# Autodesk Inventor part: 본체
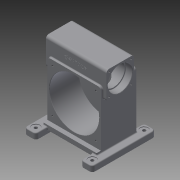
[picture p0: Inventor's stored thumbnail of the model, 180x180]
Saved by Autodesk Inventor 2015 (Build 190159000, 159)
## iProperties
Created: 2025-06
Part Number: 본체
Material: 일반
Document SubType Name: Modeling
Designer: User
Density: 1 g/cm^3
Appearance: 기본값
Author: User
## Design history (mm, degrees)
sketch "스케치4"
  geometry: L1 (-118, 110)-(-78, 110); L2 (-78, 110)-(-78, -110); L3 (-78, -110)-(-118, -110); L4 (-118, -110)-(-118, 110); L5 (78, 110)-(118, 110); L6 (118, 110)-(118, -110); L7 (118, -110)-(78, -110); L8 (78, -110)-(78, 110); 3 further points
  constraints: 16 end point, 4 parallel, 2 horizontal, 2 horizontal alignment, 2 midpoint, 2 perpendicular
  dimensions: "d1" = 40 distance of L2.end L3.end; "d2" = 220 distance of L1.end L2.end; "d3" = 118 distance from line of point (0, 0) L4; "d4" = 40 distance of L6.end L7.end; "d5" = 220 distance of L5.end L6.end; "d6" = 118 distance from line of point (0, 0) L6
extrude "돌출1" new body sketch "스케치4" distance "d7" = 20; taper "d8" = 0 deg
node "작업 평면2"
sketch "스케치5"
  geometry: L1 (93, 70)-(-93, 70); L2 (-93, 70)-(-93, -70); L3 (-93, -70)-(93, -70); L4 (93, -70)-(93, 70); L5 (93, 70)-(-93, -70); L6 (-93, 70)-(93, -70); 1 further point
  constraints: 12 end point, 2 midpoint, 2 parallel, 1 horizontal, 1 perpendicular
  dimensions: "d10" = 186 distance of L3.end L2.end; "d11" = 140 distance of L2.end L1.end
extrude "돌출2" join sketch "스케치5" distance "d12" = 206; taper "d13" = 0 deg
sketch "스케치6"
  geometry: L1 (-15, 206)-(171, 206); L2 (171, 206)-(171, 17); L3 (171, 17)-(-15, 17); L4 (-15, 17)-(-15, 206); 1 further point
  constraints: 8 end point, 2 parallel, 1 horizontal, 1 perpendicular
  dimensions: "d14" = 186 distance of L2.end L3.end; "d15" = 189 distance of L1.end L2.end
extrude "돌출3" cut sketch "스케치6" distance "d16" = 15; taper "d17" = 0 deg
sketch "스케치7"
  geometry: L1 (-15, 206)-(171, 206) reference; L2 (196, -10)-(156, -10) reference; C1 r 86 at (78, 113); 2 further points
  constraints: 1 centre point, 1 midpoint, 1 vertical alignment
  dimensions: "d18" = 172 diameter of C1; "d19" = 123 distance from line of L2 C1.centre
extrude "돌출4" cut sketch "스케치7" distance "d20" = 102; taper "d21" = 0 deg
sketch "스케치8"
  geometry: C1 r 86 at (0, 0) reference; C2 r 31 at (0, 0); 1 further point
  constraints: 1 centre point, 1 coincident
  dimensions: "d22" = 62 diameter of C2
extrude "돌출5" cut sketch "스케치8" distance "d23" = 16; taper "d24" = 0 deg
sketch "스케치9"
  geometry: C1 r 31 at (0, 0) reference; C2 r 27 at (0, 0); 1 further point
  constraints: 1 centre point, 1 coincident
  dimensions: "d25" = 54 diameter of C2
extrude "돌출6" cut sketch "스케치9" distance "d26" = 3; taper "d27" = 0 deg
fillet "모깎기1" dims "d28" = 3
fillet "모깎기2" dims "d29" = 1
chamfer "모따기1" distance "d30" = 1; stored, may be unused: second distance "d31" = 2, angle "d32" = 45 deg
chamfer "모따기2" distance "d33" = 1; stored, may be unused: second distance "d34" = 2, angle "d35" = 45 deg
sketch "스케치10"
  geometry: L1 (48, 271)-(-48, 271); L2 (-48, 271)-(-48, 175); L3 (-48, 175)-(48, 175); L4 (48, 175)-(48, 271); 2 further points
  constraints: 8 end point, 2 parallel, 1 horizontal, 1 midpoint, 1 perpendicular, 1 vertical alignment
  dimensions: "d36" = 96 distance of L3.end L2.end; "d37" = 96 distance of L2.end L1.end; "d38" = 271 distance from line of point (0, 0) L1
extrude "돌출7" join sketch "스케치10" stored distance "d39" = 210; taper "d40" = 0 deg
sketch "스케치11"
  geometry: C1 r 32 at (78, 113) reference; C2 r 86 at (78, 113); A1 r 86 centre (78, 113) between (9.502, 165) and (146.498, 165) reference; 1 further point
  constraints: 1 centre point, 1 coincident, 1 concentric
extrude "돌출8" cut sketch "스케치11" stored distance "d41" = 10; taper "d42" = 0 deg
sketch "스케치12"
  geometry: L1 (-271, 48)-(-271, -48) reference; C1 r 38.5 at (-223, 0); 1 further point
  constraints: 1 centre point, 1 horizontal alignment
  dimensions: "d43" = 77 diameter of C1; "d44" = 48 distance from line of C1.centre L1
extrude "돌출9" cut sketch "스케치12" stored distance "d45" = 10; taper "d46" = 0 deg
sketch "스케치13"
  geometry: C1 r 38.5 at (-223, 0) reference; C2 r 42.5 at (-223, 0); 1 further point
  constraints: 1 centre point, 1 coincident
  dimensions: "d47" = 85 diameter of C2
extrude "돌출10" cut sketch "스케치13" distance "d48" = 23; taper "d49" = 0 deg
fillet "모깎기3" dims "d50" = 1.1
chamfer "모따기3" distance "d51" = 1; stored, may be unused: second distance "d52" = 2, angle "d53" = 45 deg
sketch "스케치14"
  geometry: C1 r 38.5 at (223, 0) reference; C2 r 42.5 at (223, 0); 1 further point
  constraints: 1 centre point, 1 coincident
  dimensions: "d54" = 85 diameter of C2
extrude "돌출11" cut sketch "스케치14" distance "d55" = 23; taper "d56" = 0 deg
fillet "모깎기4" dims "d57" = 1.1
chamfer "모따기4" distance "d58" = 1; stored, may be unused: second distance "d59" = 2, angle "d60" = 45 deg
sketch "스케치15"
  geometry: L1 (3, 38)-(153, 38); L2 (153, 38)-(153, 188); L3 (153, 188)-(3, 188); L4 (3, 188)-(3, 38); L5 (3, 38)-(153, 188); L6 (153, 38)-(3, 188); C1 r 87 at (78, 113) reference; 1 further point
  constraints: 12 end point, 2 midpoint, 2 parallel, 1 horizontal, 1 perpendicular
  dimensions: "d61" = 150 distance of L3.end L2.end; "d62" = 150 distance of L2.end L1.end
hole "구멍1" sketch "스케치15" at (3, 188), (3, 38), (153, 38), (153, 188) diameter "d63" = 6.647; stored, may be unused: countersink angle "d67" = 90 deg, drill point angle "d69" = 118 deg; dims "d64" = 16, "d65" = 4, "d66" = 2, "d68" = 18
sketch "스케치16"
  geometry: L1 (-185, -38)-(-261, -38); L2 (-261, -38)-(-261, 38); L3 (-261, 38)-(-185, 38); L4 (-185, 38)-(-185, -38); L5 (-185, -38)-(-261, 38); L6 (-261, -38)-(-185, 38); C1 r 43.5 at (-223, 0) reference; 1 further point
  constraints: 12 end point, 2 midpoint, 2 parallel, 1 horizontal, 1 perpendicular
  dimensions: "d70" = 76 distance of L2.end L3.end; "d71" = 76 distance of L1.end L2.end
hole "구멍2" sketch "스케치16" at (-261, -38), (-185, -38), (-185, 38), (-261, 38) diameter "d72" = 4.917; stored, may be unused: countersink angle "d76" = 90 deg, drill point angle "d78" = 118 deg; dims "d73" = 12, "d74" = 4, "d75" = 2, "d77" = 14
sketch "스케치17"
  geometry: 2 further points
  dimensions: "d79" = 98 horizontal distance of point (0, 0) point (-98, -90); "d80" = 90 vertical distance of point (0, 0) point (-98, -90)
hole "구멍3" sketch "스케치17" at (-98, -90) diameter "d81" = 11; stored, may be unused: countersink angle "d85" = 90 deg, drill point angle "d87" = 118 deg; dims "d82" = 12, "d83" = 28, "d84" = 2, "d86" = 14
fillet "모깎기5" dims "d88" = 10
fillet "모깎기6" dims "d89" = 10
fillet "모깎기7" dims "d90" = 10
fillet "모깎기8" dims "d91" = 3
fillet "모깎기9" dims "d92" = 3
fillet "모깎기10" dims "d93" = 3
fillet "모깎기11" dims "d94" = 3
fillet "모깎기12" dims "d95" = 3
sketch "스케치18"
  geometry: 3 further points
  constraints: 1 vertical alignment, 1 other
  dimensions: "d96" = 30 vertical distance of point (105, -20) point (0, 10)
feature "엠보싱1" sketch "스케치18" dims "d97" = 0.5, "d98" = 0
node "솔리드1"
mirror "대칭1"
mirror "대칭2"
mirror "대칭3"
